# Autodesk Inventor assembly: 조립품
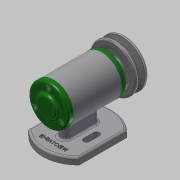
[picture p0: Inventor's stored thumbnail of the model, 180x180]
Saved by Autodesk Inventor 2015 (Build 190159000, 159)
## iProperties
Created: 2022-02
Part Number: 조립품
Document SubType Name: Assembly
Designer: 학생용
Author: 학생용
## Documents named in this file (14)
- C:\Users\학생용\Desktop\720206V1029\조립품.iam
- C:\Users\학생용\Desktop\720206V1029\본체.ipt
- C:\Users\학생용\Desktop\720206V1029\V벨트풀리.ipt
- C:\Users\학생용\Desktop\720206V1029\너트 M8.ipt
- C:\Users\학생용\Desktop\720206V1029\뒤커버.ipt
- C:\Users\학생용\Desktop\720206V1029\평와셔 8 x 17 - 복사본.ipt
- C:\Users\학생용\Desktop\720206V1029\키 3 x 3 x 12 - 복사본.ipt
- C:\Users\학생용\Desktop\720206V1029\축 - 복사본.ipt
- C:\Users\학생용\Desktop\720206V1029\오일 실 15 x 25 x 7 - 복사본.ipt
- C:\Users\학생용\Desktop\720206V1029\앞커버 - 복사본.ipt
- C:\Users\학생용\Desktop\720206V1029\스프링와셔 8 - 복사본.ipt
- C:\Users\학생용\Desktop\720206V1029\볼트 M4 x 10 - 복사본.ipt
- C:\Users\학생용\Desktop\720206V1029\베어링 6002 - 복사본.ipt
- C:\Users\학생용\Desktop\720206V1029\베어링 6002.ipt
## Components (1 placed, 1 different names)
1. V벨트풀리:1
